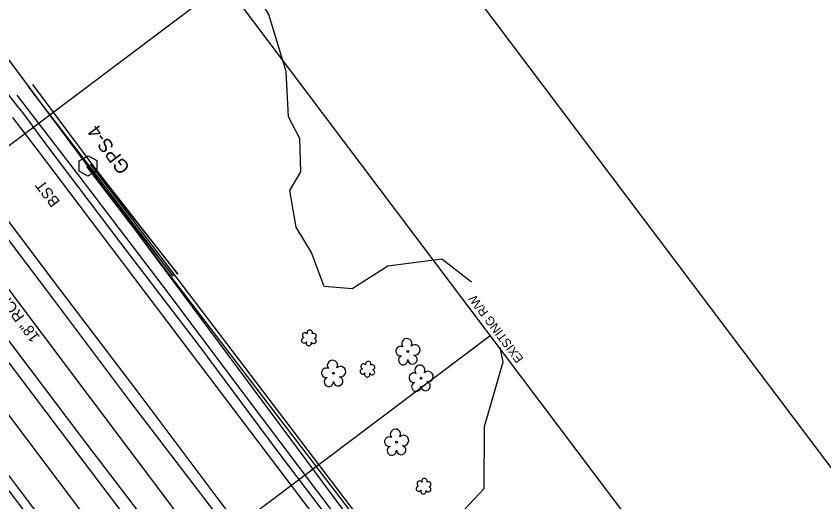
# Model space of a CAD drawing. Extents: x 1262092 to 1264624, y 774970 to 778314.
# Drawn here: x 1262309.6 to 1262603.1, y 777912.2 to 778088.7 of the extents above; entities that cross this region are included whole.
import ezdxf

# ---------------------------------------------------------------- set-up
doc = ezdxf.new("R2010")
doc.units = 0
for name, color, linetype in [('COGO Default Parcel', 7, 'Continuous'), ('CTL Primary Horizontal and Vertical CELL', 7, 'Continuous'), ('Exist Horizontal Alignment', 7, 'Continuous'), ('Exist Horizontal Alignment Tick Large', 7, 'Continuous'), ('Exist Horizontal Alignment Tick Small', 7, 'Continuous'), ('Exist Right of Way Line', 7, 'Continuous'), ('Exist Right of Way Line Text', 7, 'Continuous'), ('Exist Right of Way Width CELL', 7, 'Continuous'), ('Exist Roads EOP', 7, 'Continuous'), ('Exist Roads EOT', 7, 'Continuous'), ('Exist Structure Minor Pipes RCP 18 Inch', 7, 'Continuous'), ('Exist Structure Minor Pipes RCP 18 Inch Text', 7, 'Continuous'), ('Exist Utilities Gas UG Line SUE LOS B', 7, 'Continuous'), ('Exist Utilities Sanitary Sewer UG Line', 7, 'Continuous'), ('Exist Utilities Telephone UG FO SUE LOS B', 7, 'Continuous'), ('Prop Conc 5in Monolithic Keyed In Island', 7, 'Continuous'), ('Prop Horizontal Alignment', 7, 'Continuous'), ('Prop VPI Label', 7, 'Continuous')]:
    doc.layers.add(name, color=color, linetype=linetype)

# ---------------------------------------------------------------- blocks, each defined once
blk = doc.blocks.new('CTL PRIMARY HORIZONTAL AND VERTICAL')
at = {"layer": 'CTL Primary Horizontal and Vertical CELL'}
blk.add_line((0, 0), (0, 0), dxfattribs=at)
blk.add_lwpolyline([(-0.0646, 0.0374), (0.0004, 0.0737), (0.0654, 0.0379), (0.0644, -0.0366), (-0.0006, -0.0743), (-0.0646, -0.0381)], close=True, dxfattribs=at)

msp = doc.modelspace()

# ---------------------------------------------------------------- linework, layer by layer
at = {"layer": 'COGO Default Parcel'}
for p, q in [((1262121.77, 777902.18), (1262441.33, 778142.77)), ((1262441.33, 778142.77), (1263481.78, 776760.76))]:
    msp.add_line(p, q, dxfattribs=at)
at = {"layer": 'Exist Horizontal Alignment'}
msp.add_line((1264460.35, 775084.79), (1262255.05, 778012.66), dxfattribs=at)
at = {"layer": 'Exist Horizontal Alignment Tick Large'}
for p, q in [((1262416.07, 777971.56), (1262416.07, 777971.56)), ((1262437.33, 777960.22), (1262437.33, 777960.22)), ((1262457.74, 777917.67), (1262457.74, 777917.67))]:
    msp.add_line(p, q, dxfattribs=at)
for centre, radius, start, end in [((1262414.59, 777972.68), 0.968, 35.8908, 245.4216), ((1262416.3, 777973.6), 0.99, 334.8391, 200.4717), ((1262417.74, 777972.43), 0.929, 284.4567, 126.0861), ((1262414.27, 777970.85), 0.955, 95.1099, 327.9534), ((1262415.94, 777969.87), 0.984, 151.2797, 21.387), ((1262417.71, 777970.63), 0.937, 204.9913, 73.4601), ((1262437.56, 777962.26), 0.99, 334.8391, 200.4717), ((1262435.53, 777959.51), 0.955, 95.1099, 327.9534), ((1262435.85, 777961.35), 0.968, 35.8908, 245.4216), ((1262438.97, 777959.29), 0.937, 204.9913, 73.4601), ((1262439, 777961.09), 0.929, 284.4567, 126.0861), ((1262437.2, 777958.53), 0.984, 151.2797, 21.387), ((1262456.25, 777918.8), 0.968, 35.8908, 245.4216), ((1262457.97, 777919.71), 0.99, 334.8391, 200.4717), ((1262459.41, 777918.54), 0.929, 284.4567, 126.0861), ((1262455.94, 777916.97), 0.955, 95.1099, 327.9534), ((1262457.61, 777915.99), 0.984, 151.2797, 21.387), ((1262459.37, 777916.74), 0.937, 204.9913, 73.4601)]:
    msp.add_arc(centre, radius, start, end, dxfattribs=at)
at = {"layer": 'Exist Horizontal Alignment Tick Small'}
for p, q in [((1262451.94, 777966.8), (1262451.94, 777966.8)), ((1262424.93, 777958.9), (1262424.93, 777958.9)), ((1262456.72, 777957.14), (1262456.72, 777957.14)), ((1262447.83, 777933.89), (1262447.83, 777933.89))]:
    msp.add_line(p, q, dxfattribs=at)
for centre in [(1262451.94, 777966.8), (1262424.93, 777958.9), (1262456.72, 777957.14), (1262447.83, 777933.89)]:
    msp.add_circle(centre, 0.326, dxfattribs=at)
for centre, radius, start, end in [((1262451.56, 777969.68), 1.86, 330.1651, 219.7134), ((1262454.49, 777967.39), 1.9, 257.1011, 134.1999), ((1262449.34, 777966.96), 1.73, 62.6636, 279.3457), ((1262424.54, 777961.78), 1.86, 330.1651, 219.7134), ((1262450.24, 777963.68), 1.69, 111.5671, 6.231), ((1262453.61, 777963.9), 1.7, 181.2822, 74.56), ((1262422.32, 777959.06), 1.73, 62.6636, 279.3457), ((1262427.48, 777959.49), 1.9, 257.1011, 134.1999), ((1262456.33, 777960.02), 1.86, 330.1651, 219.7134), ((1262423.23, 777955.78), 1.69, 111.5671, 6.231), ((1262426.6, 777956), 1.7, 181.2822, 74.56), ((1262454.11, 777957.3), 1.73, 62.6636, 279.3457), ((1262459.26, 777957.73), 1.9, 257.1011, 134.1999), ((1262455.01, 777954.02), 1.69, 111.5671, 6.231), ((1262458.39, 777954.24), 1.7, 181.2822, 74.56), ((1262447.44, 777936.76), 1.86, 330.1651, 219.7134), ((1262445.22, 777934.04), 1.73, 62.6636, 279.3457), ((1262450.38, 777934.48), 1.9, 257.1011, 134.1999), ((1262446.12, 777930.77), 1.69, 111.5671, 6.231), ((1262449.5, 777930.99), 1.7, 181.2822, 74.56)]:
    msp.add_arc(centre, radius, start, end, dxfattribs=at)
at = {"layer": 'Exist Right of Way Line'}
msp.add_line((1262380.46, 778107.12), (1263428.45, 776715.75), dxfattribs=at)
at = {"layer": 'Exist Right of Way Width CELL'}
msp.add_line((1262481.82, 777972.54), (1262377.95, 777894.31), dxfattribs=at)
at = {"layer": 'Exist Roads EOP'}
for points in [[(1262311.57, 778054.09), (1262307.15, 778059.68), (1262299.95, 778069.33), (1262289.62, 778083.4), (1262284.54, 778090.33)], [(1262311.57, 778054.09), (1262320.31, 778042.27), (1262347.65, 778006.04), (1262376.01, 777968.97), (1262404.37, 777930.89), (1262432.91, 777893.24), (1262461.84, 777854.83), (1262490.86, 777816.65), (1262505.6, 777797.35)], [(1262285.77, 778035.09), (1262294.3, 778023.82), (1262322.73, 777986.32), (1262351.06, 777948.49), (1262379.86, 777910.83), (1262408.98, 777872.17), (1262437.51, 777834.34), (1262465.79, 777796.98), (1262494.21, 777759.25), (1262523.56, 777720.28), (1262551.17, 777683.56), (1262580.06, 777645.73)], [(1262533.86, 777669.85), (1262506.16, 777706.68), (1262477.25, 777744.96), (1262448.83, 777782.76), (1262448.77, 777782.75), (1262419.94, 777820.99), (1262391.44, 777858.59), (1262362.67, 777897.37), (1262333.74, 777935.31), (1262305.02, 777973.3), (1262276.84, 778010.82), (1262268.09, 778022.33)], [(1262508.59, 777649.5), (1262480.62, 777686.61), (1262451.55, 777725.45), (1262423.03, 777763.23), (1262394.37, 777801.14), (1262366.02, 777838.6), (1262337.3, 777876.52), (1262308.59, 777914.31), (1262279.57, 777952.95), (1262251.16, 777991.02), (1262242.02, 778002.99)]]:
    msp.add_lwpolyline(points, dxfattribs=at)
at = {"layer": 'Exist Roads EOT'}
for points in [[(1262308.34, 778051.79), (1262317.32, 778039.93), (1262344.37, 778004.19), (1262372.89, 777966.62), (1262401.21, 777929.2), (1262429.93, 777891.21), (1262458.73, 777853.38), (1262487.94, 777814.62), (1262517.12, 777776.18), (1262546.22, 777737.8), (1262573.92, 777700.82), (1262602.3, 777663.12)], [(1262289.2, 778037.57), (1262297.52, 778026.31), (1262325.76, 777988.99), (1262354.59, 777951.12), (1262382.95, 777913.24), (1262412.22, 777874.41), (1262440.97, 777836.5), (1262469.27, 777799.15), (1262497.42, 777761.79), (1262526.95, 777722.8), (1262554.72, 777686.15), (1262583.3, 777648.11)], [(1262530.21, 777667.14), (1262502.53, 777703.54), (1262473.57, 777742.17), (1262445.07, 777779.99), (1262416.17, 777818.02), (1262387.95, 777855.59), (1262358.59, 777894.64), (1262330.16, 777932.09), (1262301.01, 777970.53), (1262273.04, 778007.62), (1262264.28, 778019.28)], [(1262511.28, 777651.42), (1262483.32, 777688.89), (1262454.05, 777727.36), (1262425.45, 777765.13), (1262396.78, 777803.08), (1262368.42, 777840.5), (1262339.71, 777878.55), (1262311.54, 777915.71), (1262282.01, 777954.91), (1262253.58, 777992.51), (1262244.27, 778004.78)]]:
    msp.add_lwpolyline(points, dxfattribs=at)
at = {"layer": 'Exist Structure Minor Pipes RCP 18 Inch'}
msp.add_line((1262514.1, 777714.3), (1262275, 778031.81), dxfattribs=at)
at = {"layer": 'Exist Utilities Gas UG Line SUE LOS B'}
msp.add_lwpolyline([(1262994.39, 777166.73), (1262980.63, 777180.77), (1262951.12, 777219.34), (1262915.77, 777266.99), (1262883.3, 777310), (1262857.54, 777344.34), (1262828.14, 777381.91), (1262793.47, 777427.19), (1262760.54, 777472.85), (1262727.33, 777519.3), (1262694.08, 777555.83), (1262655.09, 777608.15), (1262623.1, 777653.3), (1262592.34, 777693.87), (1262575.48, 777722.21), (1262534.9, 777775.61), (1262497.72, 777820.92), (1262460.79, 777868.95), (1262430.33, 777909.82), (1262335.35, 778033.97), (1262366.66, 777994.16), (1262337.19, 778032.97), (1262314.26, 778062.88)], dxfattribs=at)
msp.add_lwpolyline([(1262994.39, 777166.73), (1262980.63, 777180.77), (1262951.12, 777219.34), (1262915.77, 777266.99), (1262883.3, 777310), (1262857.54, 777344.34), (1262828.14, 777381.91), (1262793.47, 777427.19), (1262760.54, 777472.85), (1262727.33, 777519.3), (1262694.08, 777555.83), (1262655.09, 777608.15), (1262623.1, 777653.3), (1262592.34, 777693.87), (1262575.48, 777722.21), (1262534.9, 777775.61), (1262497.72, 777820.92), (1262460.79, 777868.95), (1262430.33, 777909.82), (1262335.35, 778033.97), (1262366.66, 777994.16), (1262337.19, 778032.97), (1262314.26, 778062.88)], dxfattribs=at)
at = {"layer": 'Exist Utilities Sanitary Sewer UG Line'}
msp.add_line((1262150.97, 778282.31), (1262537.27, 777762.91), dxfattribs=at)
at = {"layer": 'Exist Utilities Telephone UG FO SUE LOS B'}
for points in [[(1262989.94, 777168.07), (1262951.99, 777219.94), (1262916.42, 777267.81), (1262888.77, 777316.31), (1262864.92, 777351.47), (1262838.91, 777387.68), (1262799.61, 777432.02), (1262765.27, 777476.73), (1262731.32, 777522.28), (1262700.44, 777560.94), (1262661.97, 777612.3), (1262627.92, 777657.64), (1262612.11, 777680.33), (1262604.08, 777687.9), (1262594.67, 777695.7), (1262574.71, 777722.66), (1262534.65, 777775.25), (1262499.34, 777822.06), (1262462.07, 777869.42), (1262431.13, 777910.63), (1262336.58, 778034.92), (1262368.35, 777994.88), (1262338.32, 778033.37), (1262315.72, 778063.86)], [(1262989.94, 777168.07), (1262951.99, 777219.94), (1262916.42, 777267.81), (1262888.77, 777316.31), (1262864.92, 777351.47), (1262838.91, 777387.68), (1262799.61, 777432.02), (1262765.27, 777476.73), (1262731.32, 777522.28), (1262700.44, 777560.94), (1262661.97, 777612.3), (1262627.92, 777657.64), (1262612.11, 777680.33), (1262604.08, 777687.9), (1262594.67, 777695.7), (1262574.71, 777722.66), (1262534.65, 777775.25), (1262499.34, 777822.06), (1262462.07, 777869.42), (1262431.13, 777910.63), (1262336.58, 778034.92), (1262368.35, 777994.88), (1262338.32, 778033.37), (1262315.72, 778063.86)], [(1262982.78, 777167.11), (1262946.46, 777216.4), (1262911.63, 777263.89), (1262904.55, 777273.66), (1262904.75, 777279.08), (1262882.68, 777309.56), (1262855.72, 777342.59), (1262826.17, 777380.64), (1262792.14, 777426.47), (1262758.72, 777471.04), (1262724.36, 777517.1), (1262692.7, 777554.83), (1262654.13, 777607.32), (1262621.89, 777651.43), (1262589.79, 777691.14), (1262572.86, 777709.66), (1262527.82, 777770.05), (1262493.25, 777818.33), (1262456.6, 777866.38), (1262426.24, 777906.46), (1262391.81, 777952.18), (1262362.73, 777991.03), (1262332.92, 778030.12), (1262309.95, 778059.98)]]:
    msp.add_lwpolyline(points, dxfattribs=at)
at = {"layer": 'Prop Conc 5in Monolithic Keyed In Island'}
for points in [[(1262475.13, 777991.95), (1262464.24, 778000.39), (1262444.63, 777997.8), (1262431.66, 777989.6), (1262421.56, 777990.43), (1262416.99, 778002.81), (1262411.38, 778012.03), (1262409.07, 778025.29), (1262413.02, 778032.03), (1262412.69, 778044.19), (1262408.56, 778052.02), (1262407.75, 778068.52), (1262401.46, 778089.29), (1262386.46, 778114.05), (1262372.11, 778134.59), (1262364.32, 778144.85), (1262358.8, 778150.49)], [(1262533.14, 777814.74), (1262522.5, 777829.79), (1262515.5, 777838.16), (1262511.37, 777849.45), (1262497.15, 777866.82), (1262485.63, 777886.53), (1262468.79, 777905.4), (1262479.72, 777917.06), (1262479.8, 777939.53), (1262486.53, 777963.05), (1262485.45, 777968.26)]]:
    msp.add_lwpolyline(points, dxfattribs=at)

# ---------------------------------------------------------------- block references
at = {"layer": 'CTL Primary Horizontal and Vertical CELL', "xscale": 50, "yscale": 50}
msp.add_blockref('CTL PRIMARY HORIZONTAL AND VERTICAL', (1262335.72, 778034.26), dxfattribs=at)
msp.add_blockref('CTL PRIMARY HORIZONTAL AND VERTICAL', (1262335.72, 778034.26), dxfattribs=at)

# ---------------------------------------------------------------- texts
at = {"layer": 'Exist Right of Way Line Text'}
msp.add_text('EXISTING R/W', height=3.2, rotation=126.9874, dxfattribs=at).set_placement((1262494.12, 777964.2))
at = {"layer": 'Exist Structure Minor Pipes RCP 18 Inch Text'}
msp.add_text('18" RCP', height=4, rotation=126.9805, dxfattribs=at).set_placement((1262318.47, 777972.03))
at = {"layer": 'Prop Horizontal Alignment'}
msp.add_text('BST', height=4, rotation=126.9874, dxfattribs=at).set_placement((1262325.75, 778021.23))
msp.add_text('BST', height=4, rotation=126.9874, dxfattribs=at).set_placement((1262325.75, 778021.23))
at = {"layer": 'Prop VPI Label'}
msp.add_text('GPS-4', height=5, rotation=126.9874, dxfattribs=at).set_placement((1262351.27, 778033.62))

doc.saveas('drawing.dxf')
